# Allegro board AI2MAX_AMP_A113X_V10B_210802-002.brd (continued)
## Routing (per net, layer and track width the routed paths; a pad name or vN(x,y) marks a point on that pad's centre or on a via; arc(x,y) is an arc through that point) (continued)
VCC5V: length 175
  TOP w0.25: C10.2 R10.2 v2(22.85,10.2)
  TOP w0.3: v2(95.75,19.1) 95.75,19.25 95.35,19.65 94.25,19.65 93.45,18.85 88.6,18.85 88.35,19.1 88.1,19.1 87.5,19.7 85.1,19.7 v2(83.53,21.27) ; UNK5R5.1 79.35,41 80.1,40.25 80.1,38.4 v2(80.2,38.3)
  TOP w0.4: v2(52.05,9.95) v2(52.65,9.35) ; v2(62.15,9.95) v2(62.75,9.35)
  TOP w0.5: v2(52.65,9.95) 51.8,10.8 51.2,10.8 ; v2(52.65,9.95) v2(52.65,9.35) v2(52.05,9.35) ; v2(52.65,9.95) v2(52.05,9.95) ; 50.67,10.37 51.03,10.37 v2(51.45,9.95) ; 50.67,10.37 C57.1 ; 50.67,10.37 50.4,10.1 ; v2(51.45,9.35) v2(52.05,9.35) ; v2(51.45,9.35) 50.43,9.35 R52.2 ; v2(51.45,9.35) v2(51.45,9.95) ; v2(52.05,9.35) 52.05,9.65 ; 61.3,10.8 C68.1 ; 61.3,10.8 C69.2 U53.5 ; 61.3,10.8 v2(62.15,9.95) ; C68.1 62.15,10.45 v2(62.15,9.95) ; C68.1 61.9,10.8 v2(62.75,9.95) ; U52.5 C58.2 49.7,10.8 ; C57.1 50.35,10.8 ; C57.1 51.2,10.8 ; C57.1 51.45,10.45 v2(51.45,9.95) ; v2(51.45,9.95) 50.55,9.95 50.4,10.1 ; v2(51.45,9.95) v2(52.05,9.95) ; v2(62.15,9.95) v2(62.15,9.35) v2(62.75,9.35) v2(62.75,9.95) ; v2(62.15,9.95) v2(62.75,9.95) ; R52.2 50.4,10.1 ; R52.2 50.67,9.65 52.05,9.65 ; 50.4,10.1 49.7,10.8 ; 50.4,10.1 50.4,10.75 50.35,10.8 ; 49.7,10.8 50.35,10.8 ; 51.2,10.8 v2(52.05,9.95) ; v2(84.6,39.1) v2(84.6,32.3) v2(84.6,26.35) ; v2(52.05,9.95) 52.05,9.65
  MID2(L3) w0.3: v2(22.85,10.2) 22.85,13.95 24.05,15.15 35,15.15 v2(40.25,9.9)
  MID2(L3) w0.5: 63.35,9.95 v2(62.75,9.95) ; 63.35,9.95 v2(62.75,9.35) ; 63.35,9.95 63.7,9.95 ; v2(62.75,9.35) 63.1,9.35 63.7,9.95 ; v2(62.75,9.35) v2(62.15,9.35) ; v2(84.6,39.1) 81,39.1 v2(80.2,38.3) ; 64.05,9.95 62.85,8.75 ; 64.05,9.95 63.7,9.95 ; 64.05,9.95 68.75,9.95 79.33,20.52 82.78,20.52 v2(83.53,21.27) 83.95,21.7 83.95,23.6 84.6,24.25 v2(84.6,26.35)
  BOTTOM w0.1: v2(84.6,32.3) 84.4,32.1 R329.1 84.35,31.35 R330.1 ; 40.9,9.4 v2(40.9,9.9) 40.9,10 40.35,10 v2(40.25,9.9) v2(40.25,9.3) ; 40.9,9.4 v2(40.9,9.3) v2(40.9,8.7) v2(40.25,8.7) v2(40.25,9.3) ; 40.9,9.4 40.35,9.4 v2(40.25,9.3)
  BOTTOM w0.2: R337.2 v2(52.65,9.35) ; R6.2 41.85,7.55 R18.1
  BOTTOM w0.25: v2(40.25,9.9) 40.25,11 R17.1 ; C13.1 42.1,10.4 R6.2
  BOTTOM w0.4: v2(95.75,19.1) 95.75,11.95 97.6,10.1 100.2,10.1 102.75,7.55 UNK5C13.2 J814.1
  BOTTOM w0.5: U3.5 C14.2 ; U51.5 C52.2 C51.1 52.65,10.45 v2(52.65,9.95) ; v2(62.75,9.35) v2(62.15,9.35) v2(62.15,9.95) ; v2(62.75,9.35) v2(62.15,9.95) ; v2(62.75,9.35) v2(62.75,9.95) v2(62.15,9.95) ; v2(84.6,39.1) 85.6,38.1 R334.1
VCC_3.3V: length 71.6
  TOP w0.25: UNK4U5.24 56.14,29.71 UNK4C4.2 ; UNK4C5.1 44.64,29.31 UNK4U5.1 ; v2(50.08,52.33) 50.14,52.27 UNK4U5.37 ; UNK4U5.12 50.14,30.43 v2(50.05,30.34)
  TOP w0.254: v1(66.95,51.23) 66.89,51.17 U1.A5 ; v1(73.68,45.21) 73.39,44.92 U1.K15
  TOP w0.3: UNK4U9.T10 v2(51,40.6) 51.01,40.59 UNK4U9.U9 ; UNK4U9.N5 v2(49.5,42.1) 49.51,42.11 UNK4U9.M6 ; v2(56.15,28.8) UNK4C4.2
  TOP w0.406: v1(66.95,51.23) 66.95,52.78 66.14,53.6 v1(66.14,56.26)
  TOP w0.5: UNK4C4.2 57.35,29.7 57.65,30 v2(57.65,33) ; 44.65,29.05 v2(45.25,28.45) v2(44.65,28.45) 44.65,29.05 ; 44.65,29.05 UNK4C5.1 ; v2(85.2,51.7) v2(85.2,54.15) ; v2(45.5,62.35) v2(45.5,59.1)
  MID2(L3) w0.5: v2(85.2,51.7) 84.75,51.7 81.8,48.75 80.75,48.75 78.25,46.25 74.72,46.25 v1(73.68,45.21)
  BOTTOM w0.2: UNK2R18.1 v2(54.7,58.8) ; UNK2R19.1 v2(54.7,55.5)
  BOTTOM w0.3: UNK4C8.2 50.06,52.3 v2(50.08,52.33)
  BOTTOM w0.381: v1(73.68,45.21) 73.92,44.98 UNK5C10.2 ; UNK2C22.2 66.85,51.13 v1(66.95,51.23)
  BOTTOM w0.4: UNK4C17.2 v2(49.5,42.1) ; UNK4C18.2 51.25,40.35 v2(51,40.6)
  BOTTOM w0.5: UNK4R6.2 v2(54.25,36.05) 55.05,36.05 56.25,34.85 U55.1 C79.1 58,34.5 58,33.35 v2(57.65,33) 57.6,32.95 U55.3 ; 44.65,29.55 C22.1 Q1.3 ; 44.65,29.55 44.95,29.25 ; 44.65,29.55 v2(44.65,28.45) 44.95,28.45 ; v2(45.5,62.35) 44.5,63.35 UNK2T15.1 ; 44.95,29.25 45.25,28.95 v2(45.25,28.45) 44.95,28.45 ; 44.95,29.25 44.95,28.45 ; v2(56.15,28.8) 50.35,28.8 50.05,29.1 UNK4C49.2 v2(50.05,30.34)
VDD_EE: length 111.8
  TOP w0.2: R53.2 C64.2 UNK1R2.2 45.4,5.05 v2(45.2,5.05) ; v2(40,19.3) 40,22.45 v2(39.8,22.65)
  TOP w0.254: U1.J5 67.12,45.8 67.28,45.8 67.52,45.55 ; U1.J5 v1(66.56,45.86) U1.J4 v1(65.91,45.85) U1.J3 ; U1.J5 67.2,45.26 v1(67.22,45.29) 67.23,45.3 67.27,45.3 67.52,45.55 ; 67.52,45.55 U1.J6
  TOP w0.3: U1.K11 v1(70.47,45.24) ; U1.F12 v1(71.12,47.2)
  TOP w0.5: v2(57.65,45.75) v2(57.65,45.15)
  MID2(L3) w0.2: 51.65,15.5 51.35,15.2 ; 51.65,15.5 51.35,15.8 ; 51.65,15.5 51.65,15.2 ; 51.35,15.2 51.65,14.9 ; 51.35,15.2 v2(50.9,15.65) ; 51.35,15.2 51.65,15.2 ; 51.35,15.2 51.35,15.8 ; 51.65,14.9 51.65,15.2 ; 51.65,14.9 54.35,12.2 68.2,12.2 82.35,26.35 v2(83.1,26.35) ; v2(50.9,16.25) 51.35,15.8
  MID2(L3) w0.3: v1(70.47,45.24) 69.85,45.86 v1(66.56,45.86)
  BOTTOM w0.1: UNK2C13.1 61.58,45.51 61.44,45.65 ; 62.9,45.85 62.9,45.85 UNK2C11.2
  BOTTOM w0.2: 50.9,15.05 50.67,15.28 ; 50.9,15.05 50.9,15.5 ; 50.9,15.05 50.9,12.15 50.1,11.35 50.1,5.95 49.2,5.05 v2(45.2,5.05) ; 50.67,15.28 v2(50.3,15.65) ; 50.67,15.28 50.9,15.5 ; R15.2 38.8,18.1 v2(40,19.3) ; 50.9,15.5 v2(50.9,15.65) ; v2(83.1,26.35) 83.65,26.9 86.4,26.9 R333.2 ; v1(71.12,47.2) 71.35,46.96 UNK2R27.2 ; v2(39.8,22.65) v2(50.6,22.65)
  BOTTOM w0.3: UNK2C1.2 71.37,47.45 v1(71.12,47.2) 70.66,46.74 UNK2C16.2
  BOTTOM w0.381: UNK2C20.2 67.09,45.85 67.22,45.72 v1(67.22,45.29)
  BOTTOM w0.4: v1(70.47,45.24) 70.47,45.63 UNK2C16.2
  BOTTOM w0.5: v2(50.9,15.65) v2(50.3,15.65) v2(50.3,16.25) ; v2(50.9,15.65) v2(50.9,16.25) v2(50.3,16.25) ; v2(50.9,15.65) v2(50.3,16.25) ; 58.15,45.65 v2(57.65,45.15) v2(57.65,45.75) 57.8,45.9 59.15,45.9 59.15,45.65
  BOTTOM w0.508: 61.58,45.52 61.58,45.85 v1(65.91,45.85) UNK2C20.2
  BOTTOM w1.016: 58.15,45.65 61.44,45.65
VDDAO_3.3V: length 209
  TOP w0.1: v2(38.5,22.95) 38.5,23.65 38.9,24.05 R350.1 R351.1 ; UNK2R28.1 UNK2R24.1 v2(79.95,59.8)
  TOP w0.2: 43.33,15.28 v2(42.95,15.65) ; 43.33,15.28 43.55,15.05 ; 43.33,15.28 43.55,15.5 ; v2(45.2,5.92) 44.42,5.92 44,6.35 44,13.3 43.55,13.75 43.55,15.05 ; 43.55,15.5 v2(43.55,15.65) ; 43.55,15.5 43.55,15.05 ; R62.1 63.3,8.4 63.75,8.85 v2(63.75,11.2)
  TOP w0.25: R348.1 R349.1 93.55,59.1 v2(92.7,58.25)
  TOP w0.254: v1(73.07,44.59) U1.K14 ; U1.D13 72.09,48.82 v1(71.77,49.15)
  TOP w0.3: v2(61.6,61.45) UNK2D7.1 ; v2(92.7,58.25) 92.85,58.1 92.85,49.8 v2(92.95,49.7)
  TOP w0.4: v2(60.15,58) 60.15,57.2 60.55,56.8 60.55,52.95 v2(61.25,52.25)
  TOP w0.5: v3(74.05,56.05) 74.05,57.2 UNK2U2.3 74.73,59.37 v2(74.55,59.55) UNK2C15.2 ; v2(83.95,37.9) v2(83.95,32.3) v2(83.95,27.35) ; v2(43.55,16.25) v2(42.95,16.25) v2(42.95,15.65) ; v2(43.55,16.25) v2(42.95,15.65) ; v2(43.55,16.25) v2(43.55,15.65) v2(42.95,15.65) ; v2(51.2,71.4) v2(50.6,71.4) ; v2(43.35,34.55) v2(43.35,35.15)
  MID2(L3) w0.2: v2(92.95,49.7) 92.55,49.3 92.55,42.8 87.65,37.9 v2(83.95,37.9) ; 43.7,14.9 43.4,15.2 ; 43.7,14.9 43.7,12.55 45.05,11.2 v2(63.75,11.2) ; 43.7,14.9 43.7,15.2 ; 43.4,15.2 43.7,15.2 ; 43.4,15.2 v2(42.95,15.65) ; 43.4,15.2 43.7,15.5 ; 43.4,15.2 43.4,15.5 v2(43.55,15.65) 43.7,15.5 ; 43.7,15.2 43.7,15.5
  MID2(L3) w0.5: 51.2,70.8 v2(51.2,71.4) v2(50.6,71.4) 51.2,70.8 ; 51.2,70.8 52.2,69.8 52.2,61 ; UNK2CON1.3 66.35,71.42 66.35,61.7 ; v2(83.95,27.35) 84.3,27.7 v2(93.35,27.7) 94.52,27.7 v2(96.1,26.12)
  BOTTOM w0.1: R336.1 81.5,32.3 v2(83.95,32.3)
  BOTTOM w0.2: v2(96.1,26.12) 96.12,26.14 R214.2 ; C19.2 R8.2 47.5,6.8 46.63,5.92 v2(45.2,5.92) ; R314.2 33.93,59.01 v2(33.95,59.03) ; R323.1 33.93,47.07 v2(33.95,47.05) ; v2(33.95,25.1) 33.93,25.12 R307.1
  BOTTOM w0.254: v1(71.77,49.15) 71.86,49.18 72.51,49.84 UNK2C5.2
  BOTTOM w0.3: U201.40 94.68,50.08 C201.1 92.96,49.69 v2(92.95,49.7) ; UNK2C5.2 73.48,51.28 73.48,51.28 ; v2(36.8,57.4) C330.1 35.37,57.01 U302.40 ; U301.40 35.37,35.06 C301.1 v2(36.55,35.45) ; U202.40 94.68,28.13 C230.1 93.39,27.74 v2(93.35,27.7)
  BOTTOM w0.305: C101.2 75.59,44.45 73.21,44.45 v1(73.07,44.59)
  BOTTOM w0.4: v2(78.55,61) 77.66,61 T129.1 T319.1 ; v2(61.25,52.25) 63.11,50.39 UNK2R2.1
  BOTTOM w0.5: 42.7,34.5 42.05,33.85 41.8,33.85 ; 42.7,34.5 41.8,34.5 ; 42.7,34.5 43.1,34.9 ; 43.1,34.9 R12.2 41.8,34.5 ; 43.1,34.9 v2(43.35,35.15) v2(43.35,34.55) 42.65,33.85 C21.1 ; 41.8,33.85 C23.2 C21.1 ; 41.8,33.85 41.8,34.5 ; v2(50.6,71.4) v2(51.2,71.4) C249.1 51.85,71.35 C250.2 51.85,67.9 T316.1 ; 41.8,34.5 C21.1 ; C21.1 42.65,32.3 Q1.2 ; v2(83.95,37.9) 83.95,37.3 R335.1 83.65,37.15 82.7,36.2 79.8,36.2 79.3,36.7 79.3,39.4 77.27,41.43 77.27,42.77 C101.2 ; R105.1 62.7,56.86 v2(62.7,57.85)
  BOTTOM w0.508: v3(74.05,56.05) 74.32,55.78 74.32,52.12 73.48,51.28
VDDCPU: length 53.9
  TOP w0.2: v1(67.18,47.2) 67.21,47.2 ; 67.21,47.2 U1.F6 67.54,47.52 67.86,47.2 67.86,47.19 U1.G6 ; 67.21,47.2 U1.G5 ; 67.21,47.2 U1.F5 66.56,47.2 ; 67.21,47.2 U1.G6 ; v2(53.8,15.05) 53.8,14.55 54.4,13.95 54.4,6.65 54.75,6.3 v2(58.95,6.3) ; v1(67.83,46.59) 67.87,46.55 67.86,46.55 U1.G6 ; 66.56,46.55 U1.G5 ; 66.56,46.55 U1.H4 v1(65.92,46.6) ; 66.56,46.55 U1.H5 U1.G6 ; 66.56,46.55 66.4,46.71 ; 66.56,46.55 v1(66.58,46.59) ; U1.G5 67.21,46.59 v1(67.19,46.59) ; U1.G5 66.56,47.2 ; v1(65.92,46.6) U1.G4 ; v1(65.92,46.6) U1.H3 ; v1(65.92,46.6) U1.G3 65.59,46.87 v1(65.91,47.2) U1.G4 ; U1.G4 66.4,46.71 ; U1.G4 66.4,46.71 ; U1.G4 66.56,47.2
  TOP w0.5: v2(53.2,16.25) v2(53.2,15.65) ; v2(53.2,16.25) v2(53.8,15.65) ; v2(53.2,16.25) v2(53.8,16.25) v2(53.8,15.65) ; v2(53.2,15.65) v2(53.8,15.05) ; v2(53.2,15.65) v2(53.2,15.05) v2(53.8,15.05) ; v2(53.2,15.65) v2(53.8,15.65) ; v2(57.45,50.7) v2(58.05,50.1) ; v2(57.45,50.7) v2(57.45,50.1) v2(58.05,50.1) ; v2(57.45,50.7) v2(58.05,50.7) ; v2(58.05,50.1) v2(58.65,50.1) ; v2(58.05,50.1) v2(58.05,50.7) ; v2(58.05,50.7) v2(58.65,50.7) v2(58.65,50.1) ; v2(58.05,50.7) v2(58.65,50.1) ; v2(53.8,15.05) v2(53.8,15.65)
  BOTTOM w0.1: v1(65.92,46.6) 65.91,46.61 v1(65.91,47.2) ; v1(67.18,47.2) UNK2C19.2 ; 66.7,46.54 66.65,46.59 v1(66.58,46.59) ; UNK2C6.1 UNK2C4.1 ; 63.2,46.89 63.22,46.91 UNK2C7.2 ; 65.4,46.89 65.38,46.91 UNK2C14.2 ; UNK2C8.2 64.31,46.9 64.3,46.89
  BOTTOM w0.102: 67.84,46.56 67.82,46.55 ; 67.84,46.56 67.83,46.57 ; 67.84,46.56 67.85,46.55 67.84,46.56 ; 67.84,46.56 v1(67.83,46.59) ; 67.84,46.56 67.84,46.56 ; 67.82,46.55 67.79,46.51 ; 67.82,46.55 v1(67.83,46.59) ; 67.84,46.56 v1(67.83,46.59) ; 67.84,46.56 67.94,46.66 v1(67.83,46.59) ; 67.51,46.89 67.83,46.57 ; v1(67.83,46.59) 67.83,46.57
  BOTTOM w0.2: v1(67.83,46.59) 67.71,46.7 UNK2C19.2 ; UNK2C2.2 66.57,47.01 66.7,46.89 ; v2(58.95,6.3) 58.05,6.3 UNK1R1.2 R51.2 C63.2
  BOTTOM w0.254: 65.93,46.54 65.93,46.65 v1(65.92,46.6) 65.93,46.54 ; 65.93,46.54 66.34,46.54 66.7,46.89
  BOTTOM w0.406: 67.86,46.61 67.86,46.59 v1(67.83,46.59) 67.84,46.57
  BOTTOM w0.508: v1(67.19,46.59) v1(67.83,46.59) ; v1(67.83,46.59) 67.82,46.58 ; v1(67.83,46.59) 67.79,46.51 67.76,46.54 66.34,46.54
  BOTTOM w1.27: UNK2C4.1 62.13,46.89 67.51,46.89
VDDCPU_EN: length 97.4
  TOP w0.1: v2(60.25,51.85) 60.05,52.05 57.75,52.05 56.85,52.95 56.85,55.65 56.15,56.35 56.15,57.5 55.3,58.35 54.2,58.35 v2(53.55,59) ; v2(52,7.45) 53.05,7.45 53.6,8 53.6,13.2 52.3,14.5 52.3,16.8 53.95,18.45 v2(53.95,23.9) ; v2(41.5,56.25) 42.15,55.6 42.15,27.25 43,26.4 v2(43,23.7)
  TOP w0.102: U1.C4 v1(65.91,49.8)
  BOTTOM w0.1: v1(65.91,49.8) 65.31,50.4 64.26,50.4 UNK2R2.2 63.76,49.89 62.94,49.89 60.97,51.85 v2(60.25,51.85) ; v2(43,23.7) 43.3,23.4 48.5,23.4 49,23.9 v2(53.95,23.9) ; v2(41.5,56.25) 41.5,56.75 42,57.25 52.8,57.25 53.55,58 v2(53.55,59)
  BOTTOM w0.2: R54.1 v2(52,7.45)
VDDCPU_PWM: length 94.4
  TOP w0.1: v2(43.2,4.6) 42.95,4.85 42.95,12.6 41.65,13.9 41.65,22.95 40.95,23.65 40.95,53.75 v2(40.75,53.95)
  TOP w0.102: v1(65.26,49.15) U1.D3
  BOTTOM w0.1: v2(40.75,53.95) 42.35,53.95 43.85,55.45 52.8,55.45 54.05,54.2 56.25,54.2 60.3,50.15 62.02,50.15 62.85,49.32 65.09,49.32 v1(65.26,49.15)
  BOTTOM w0.2: UNK1R1.1 R56.2 56.9,4.85 56.25,4.2 43.6,4.2 v2(43.2,4.6)
VDDEE_PWM: length 84
  TOP w0.1: v2(40.75,54.95) 40.95,54.95 41.55,54.35 41.55,24.25 42.15,23.65 42.15,14.2 43.45,12.9 43.45,5.7 44.6,4.55 45.55,4.55 46.05,5.05 UNK1R2.1 R58.2
  TOP w0.102: v1(65.91,49.15) U1.D4
  BOTTOM w0.1: v2(40.75,54.95) 42.55,54.95 43.55,55.95 53.01,55.95 54.26,54.7 56.45,54.7 60.25,50.9 61.61,50.9 62.95,49.56 65.5,49.56 v1(65.91,49.15)
VDDIO_AO18: length 88.9
  TOP w0.254: v1(71.77,45.9) U1.H13 72.33,45.97 v1(72.33,45.9) 72.33,45.81 U1.J13 71.96,45.7 v1(71.77,45.9) ; v1(71.77,45.9) U1.J12 ; v1(71.77,45.9) U1.H12
  TOP w0.5: v2(85.95,54.1) v2(85.95,51.7) 85.95,47.3 84.55,45.9 84.55,40.85 v2(83.95,40.25)
  MID2(L3) w0.5: v2(61.57,57.85) 62.32,57.1 69,57.1 69.8,57.9 74.58,57.9 v3(75.28,57.2) 76.43,56.05 84.3,56.05 85.95,54.4 v2(85.95,54.1)
  BOTTOM w0.1: v1(71.77,45.9) 71.77,45.9 v1(72.33,45.9) ; 74.6,46.26 UNK3C1.2 ; UNK2C17.1 77.04,46.27 77.05,46.28
  BOTTOM w0.254: UNK5C9.2 72.09,45.7 72.68,45.7 72.87,45.9
  BOTTOM w0.3: UNK2R29.2 79.45,49.05 81.55,51.15 85.4,51.15 v2(85.95,51.7)
  BOTTOM w0.4: UNK5C9.2 71.77,45.5 v1(71.77,45.9) 72.87,45.9 72.88,45.9
  BOTTOM w0.406: 72.88,45.9 UNK2C10.2
  BOTTOM w0.5: U54.5 C76.1 UNK5R20.1 ; v2(61.57,57.85) R106.1 ; v2(83.95,40.25) UNK5R20.1 ; UNK5R20.1 82.25,41.26 79.6,43.91 79.6,44.91
  BOTTOM w0.508: 75.34,46.26 UNK2C12.2 ; 75.34,46.26 74.6,46.26 74.32,45.98 ; 75.34,46.26 75.24,46.16 ; 75.34,46.26 76.68,46.26 76.78,46.16 ; UNK2C10.2 72.95,45.98 74.32,45.98 ; 74.32,45.98 75.05,45.98 75.24,46.16 ; v3(75.28,57.2) 75.61,56.87 75.61,53.93 UNK2R3.2 ; 76.78,46.16 UNK2C17.1 ; 76.78,46.16 75.24,46.16
  BOTTOM w0.61: 78.33,46.18 77.72,46.18 77.61,46.28 ; 78.33,46.18 79.6,44.91 79.6,45.42 78.45,46.56 UNK2C12.2 ; 78.33,46.18 78.23,46.28 77.61,46.28 ; 77.61,46.28 77.05,46.28
VDDIO_BOOT: length 92.4
  TOP w0.2: UNK4U9.Y4 UNK4U9.AA5 v2(49.01,36.95) ; UNK4U9.Y4 UNK4U9.W4 ; UNK4U9.Y4 UNK4U9.AA3 v2(48.01,36.95) ; UNK4R3.1 UNK4R8.1 51.49,54.48 v2(51.61,54.36)
  TOP w0.25: v2(54.8,53.46) UNK4C11.2 54.64,52.59 UNK4U5.28 ; v2(45.65,52.45) 46.14,51.96 UNK4U5.45
  TOP w0.254: UNK4U5.34 51.64,53.57 UNK4C10.2 51.61,53.64 v2(51.61,54.36)
  TOP w0.3: v2(49.7,43.1) 49.51,43.29 UNK4U9.K6 ; v1(65.32,44.53) 65.58,44.27 U1.L3
  TOP w0.5: v2(58.75,41.65) 58.25,41.15 v2(58.25,37.45) ; v2(43.95,38.95) v2(43.95,44.25) v2(43.95,51.3)
  MID2(L3) w0.5: 48.2,36.95 v2(49.01,36.95) 50.15,36.95 50.95,36.15 v2(50.95,35.2) ; 48.2,36.95 v2(48.01,36.95) 46.2,38.76 ; 48.2,36.95 v2(46.2,38.95) ; 46.01,38.95 v2(46.2,38.95) ; 46.01,38.95 46.2,38.76 ; 46.01,38.95 v2(43.95,38.95) ; v2(46.2,38.95) 46.2,38.76 ; v2(49.7,43.1) 49.7,43.9 49.35,44.25 43.95,44.25 v2(43.95,44.25)
  BOTTOM w0.1: v2(50.95,35.2) 50.95,31.9 UNK4R4.1 ; UNK4R12.2 v2(46.2,38.95) ; UNK4C34.2 50.25,43.6 UNK4R16.1
  BOTTOM w0.2: v2(48.01,36.95) 47.55,36.49 UNK4R14.1 UNK4R1.2 48.65,36.95
  BOTTOM w0.4: v2(58.75,41.65) 60.35,41.65 60.9,42.2 61.72,42.2 63.03,43.51 63.47,43.51 UNK4C2.2 64.49,44.19 64.83,44.53 v1(65.32,44.53) ; UNK4C34.2 49.8,43.2 v2(49.7,43.1)
  BOTTOM w0.5: v2(43.95,51.3) 44.45,51.8 UNK4C48.2 v2(45.65,52.45) 45.65,52.75 46.48,53.58 49.37,53.58 50.15,54.36 v2(51.61,54.36) 52.14,54.36 53.04,53.46 v2(54.8,53.46) ; v2(58.25,37.45) 57.75,36.95 UNK4R6.1 UNK4R5.1 UNK4C47.1 UNK4C35.2 v2(49.01,36.95) v2(48.01,36.95)
VDDIO_X: length 12.4
  TOP w0.254: U1.C8 68.84,49.47 v1(69.16,49.8)
  BOTTOM w0.4: v1(69.16,49.8) 69.16,50.14 68.6,50.7 C102.2 68.6,53.5 68.1,54 66.75,54 65.2,55.55 63.4,55.55 63.01,55.94 R105.2 R106.2
VDDQ1.35V: length 76.3
  TOP w0.2: 70.18,32.73 v1(70.56,32.35) 70.15,31.94 UNK3U1.E9 v1(69.77,32.31) 70.15,32.69 UNK3U1.D9 70.18,32.73 ; 70.18,32.73 70.2,32.73 v1(70.62,33.15) 70.53,33.15 UNK3U1.C9 ; v1(70.62,29.59) 70.21,29.59 70.15,29.54 UNK3U1.H9 ; UNK3U1.F1 63.54,31.13 63.28,31.4 63.27,31.4 v1(63.23,31.43) ; U1.M11 v1(70.47,43.94) U1.M10 ; UNK3U1.R9 70.16,23.94 70.68,23.94 v1(70.68,23.94) ; U1.M6 v1(67.86,43.29) U1.M7 68.19,43.62 v1(68.51,43.29) U1.M8 ; v1(70.67,25.53) 70.67,25.53 UNK3U1.N9 ; UNK3U1.C1 63.15,33.53 v1(63.15,33.53) ; UNK3U1.H2 v1(64.19,29.17) ; v1(68.91,35.54) 68.94,35.54 UNK3U1.A8 ; v1(63.19,23.83) 63.29,23.93 UNK3U1.R1 ; UNK3U1.A1 63.76,35.13 v1(64.15,34.74) 64.55,34.34 UNK3U1.B2 v1(64.92,34.7) ; v1(68.12,30.71) 68.17,30.71 UNK3U1.G7 68.27,30.05 v1(68.09,30.05) ; UNK3U1.K2 64.55,27.94 v1(64.92,28.31) ; C74.2 R61.2 59.45,7.35 60,6.8 v2(60,6.3) ; v1(68.94,27.52) UNK3U1.K8 ; 66.89,42.97 U1.N5 v1(66.56,42.64) 66.24,42.97 U1.N4 v1(66.56,43.29) 66.89,42.97
  TOP w0.3: v1(63.18,25.52) 63.74,25.52 UNK3U1.N1 ; UNK3U1.D2 64.94,32.34 v1(64.96,32.34)
  BOTTOM w0.2: 61,13.15 61,7.3 v2(60,6.3) ; 61,13.15 61.23,13.38 ; 61,13.15 61,13.6 ; 61.23,13.38 61,13.6 ; 61.23,13.38 v2(61.6,13.75) ; 61,13.6 v2(61,13.75)
  BOTTOM w0.3: 70.86,33.39 UNK3C58.2 70.73,33.96 70.6,33.96 ; 70.86,33.39 v1(70.62,33.15) 70.32,32.85 UNK3C38.2 ; 70.86,33.39 70.86,32.65 70.6,32.39 ; 70.1,32.35 70.3,32.55 70.3,33.96 ; 70.1,32.35 69.81,32.35 ; 70.1,32.35 v1(70.56,32.35) 70.6,32.39 ; UNK3C38.2 69.8,33.95 UNK3C42.2 70.1,33.96 ; UNK3C38.2 69.77,32.82 v1(69.77,32.31) 69.81,32.35 ; 70.6,32.39 70.6,33.96 ; 70.1,33.96 70.3,33.96 ; 70.1,33.96 70.1,32.64 69.81,32.35 ; v1(63.15,33.53) 63.5,33.18 UNK3C21.2 ; v1(70.47,43.94) 71.04,43.37 UNK3C4.2 ; 70.6,33.96 70.3,33.96
  BOTTOM w0.381: v1(63.23,31.43) 62.92,31.74 UNK3C2.2
  BOTTOM w0.4: UNK3C9.2 64.15,35.12 v1(64.15,34.74) ; UNK3C30.2 71.12,25.53 v1(70.67,25.53) ; UNK3C19.2 63.88,29.49 v1(64.19,29.17) ; UNK3C12.2 70.42,24.21 v1(70.68,23.94) ; 66.56,42.71 66.56,43.16 ; 66.56,42.71 67.03,43.18 UNK3C39.2 ; 66.56,42.71 v1(66.56,42.64) 65.66,42.64 UNK3C62.2 ; 66.56,43.16 v1(66.56,43.29) 66.63,43.36 UNK3C39.2 ; 66.56,43.16 66.05,42.65 ; UNK3C39.2 66.32,42.65 66.05,42.65 ; UNK3C18.2 63.16,25.5 v1(63.18,25.52) 63.3,25.52 UNK3C6.1 ; UNK3C28.1 63.15,40.28 UNK3C31.2 64.85,41.85 UNK3C62.2 ; UNK3C62.2 66.05,42.65 ; v1(70.62,29.59) 70.12,29.59 UNK3C45.2 ; v1(68.12,30.71) 67.66,30.71 UNK3C8.1 67.56,30.05 v1(68.09,30.05) ; v1(64.92,34.7) 64.92,35.18 UNK3C10.2 ; v1(61.44,26.9) 61.44,27.49 UNK3R19.2 61.37,27.56 v1(60.84,27.56) ; v1(64.96,32.34) 65.01,32.28 UNK3C11.2 ; v1(64.92,28.31) 64.92,28.7 UNK3C26.1
  BOTTOM w0.406: v1(68.51,43.29) 67.87,43.29 v1(67.86,43.29)
  BOTTOM w0.5: v1(68.91,35.54) 69.01,35.64 UNK3C20.2 ; 63.19,23.42 63.67,23.42 UNK3R8.2 ; 63.19,23.42 UNK3C35.2 ; 63.19,23.42 v1(63.19,23.83) ; UNK3R8.2 63.65,23.37 v1(63.19,23.83) ; UNK3R8.2 63.72,24.24 ; v2(61.6,13.75) v2(61,13.75) v2(61,14.35) ; v2(61.6,13.75) v2(61,14.35) ; v2(61.6,13.75) v2(61.6,14.35) v2(61,14.35) ; v1(68.51,43.29) 68.48,43.33 UNK3C5.2 ; UNK3C26.1 65.2,29.2 64.7,29.7 UNK3C19.2 ; v1(63.19,23.83) 63.31,23.83 63.72,24.24 ; 63.72,24.24 UNK3C6.1
  vias: v4(60.83,38.06) v4(60.85,39.07)
ACTIVE_STBY: length 123.9
  TOP w0.1: v2(59.5,24.2) 59.8,24.2 60.35,23.65 60.35,23.25 66,17.6 66,17.15 66.25,16.9 66.8,16.9 v2(67.2,16.5) ; v2(44.8,25.4) 44.3,25.9 43.8,25.9 42.35,27.35 42.35,56.05 v2(42.15,56.25) ; U1.B11 71.12,50.45 71.12,50.93 70.68,51.36 70.68,54.98 71.45,55.75 71.45,58.85 v2(71.25,59.05) ; v2(78.14,15.5) 78.3,15.5 79.1,16.3 85.95,16.3 87.5,14.75 R219.1
  BOTTOM w0.1: v2(71.25,59.05) 57.25,59.05 56.95,59.35 54.6,59.35 54.3,59.05 54.3,58.15 53,56.85 42.75,56.85 v2(42.15,56.25) ; v2(67.2,16.5) 67.4,16.3 76.64,16.3 77.04,15.9 77.74,15.9 v2(78.14,15.5) ; R320.1 44.25,25.95 v2(44.8,25.4) 44.8,24.8 45.3,24.3 47.2,24.3 48.5,25.6 57.5,25.6 58.5,24.6 59.1,24.6 v2(59.5,24.2)
AMP_RESET: length 105.2
  TOP w0.1: v2(67.2,17.3) 66.8,17.7 66.47,17.7 60.75,23.42 60.75,23.85 59.6,25 v2(59.5,25) ; v2(42.35,60.2) 42.2,60.05 42.2,57.45 42.75,56.9 42.75,27.55 43.95,26.35 46.8,26.35 v2(47.15,26) ; R215.1 v2(88.5,13.4) 88.5,14.35 86.15,16.7 78.8,16.7 78.4,16.3 v2(78.14,16.3)
  BOTTOM w0.1: v2(67.2,17.3) 67.25,17.3 67.85,16.7 77.74,16.7 v2(78.14,16.3) ; v2(42.35,60.2) 42.1,59.95 40.35,59.95 40.05,60.25 40.05,63.9 42.8,66.65 48.1,66.65 48.58,67.12 ; R315.1 v2(47.15,26) 58.5,26 v2(59.5,25) ; UNK5R74.2 v2(88.5,13.4)
  BOTTOM w0.3: T317.1 48.58,67.12
AMP_SCL: length 67.5
  TOP w0.1: UNK2R24.2 v2(81.5,59.05) ; v2(87.25,59) 87.25,57.8 87.8,57.25 87.8,54.25 88.35,53.7 88.35,48.25 88.6,48 88.6,33.55 89.4,32.75 89.4,20.1 v2(89.6,19.9)
  TOP w0.102: U1.A16 74.04,51.69 75.8,53.46 75.8,54.57 78.36,57.14 81.24,57.14 81.9,57.8 81.9,58.65 v2(81.5,59.05)
  BOTTOM w0.1: UNK5R66.2 87.4,15.6 86.7,16.3 86.7,18.25 88.15,19.7 89.4,19.7 v2(89.6,19.9) ; v2(87.25,59) 86.25,59 85.65,59.6 82.85,59.6 R209.1 v2(81.5,59.05)
AMP_SCL_DEV: length 66.1
  TOP w0.1: v2(43.3,60.9) 43.05,60.65 43.05,59.45 v2(42.65,59.05) ; v2(52.3,58.45) 52.3,58.25 52.85,57.7 R309.1 ; v2(83.8,61.3) 83.95,61.15 83.95,59.25 v2(83.75,59.05)
  BOTTOM w0.1: v2(43.3,60.9) 43.7,61.3 43.7,63.85 44.1,64.25 52.6,64.25 53.15,64.8 68.15,64.8 69.15,65.8 69.7,65.8 70.6,66.7 74.55,66.7 75.7,67.85 76.1,67.85 ; v2(83.8,61.3) 83.6,61.5 81.7,61.5 79.1,64.1 79.1,66.8 78.05,67.85 77.7,67.85 ; R238.1 v2(83.75,59.05) R209.2 ; v2(42.65,59.05) 43.05,58.65 43.5,58.65 43.65,58.5 44.2,58.5 44.65,58.05 51.9,58.05 v2(52.3,58.45)
  BOTTOM w0.3: 76.1,67.85 T306.1 77.7,67.85
AMP_SDA: length 69.5
  TOP w0.1: v2(90.25,19.9) 89.6,20.55 89.6,32.87 88.8,33.67 88.8,48.15 88.55,48.4 88.55,53.8 88.01,54.34 88.01,57.74 v2(87.75,58) ; 78.27,57.35 80.25,57.35 UNK2R28.2 v2(81.5,57.95)
  TOP w0.102: U1.B15 73.39,50.27 73.71,50.59 73.71,51.67 75.59,53.55 75.59,54.66 78.27,57.35
  BOTTOM w0.1: v2(87.75,58) 87.55,58.2 86.5,58.2 85.7,57.4 82.85,57.4 R210.1 v2(81.5,57.95) ; UNK5R65.2 87.4,13.3 87.95,13.85 87.95,15.35 86.9,16.4 86.9,18.15 88.25,19.5 89.85,19.5 v2(90.25,19.9)
AMP_SDA_DEV: length 69.4
  TOP w0.1: R310.1 52.5,57.1 52.5,57.45 51.7,58.25 v2(51.7,58.45) ; v2(84.45,61.3) 84.15,61 84.15,58.35 v2(83.75,57.95) ; v2(43.3,61.5) 43.7,61.1 43.7,60.7 43.25,60.25 v2(43.25,59.05)
  BOTTOM w0.1: R210.2 v2(83.75,57.95) R239.1 ; v2(84.45,61.3) 84.05,61.7 81.8,61.7 79.3,64.2 79.3,67.2 ; 78.72,68.42 78.5,68.65 76.2,68.65 74.45,66.9 70.5,66.9 69.6,66 69.05,66 68.05,65 53.05,65 52.5,64.45 43.95,64.45 43.5,64 43.5,61.7 v2(43.3,61.5) ; v2(43.25,59.05) 43.4,59.05 43.75,58.7 44.35,58.7 44.8,58.25 51.5,58.25 v2(51.7,58.45)
  BOTTOM w0.3: 78.72,68.42 T305.1 79.3,67.2
BCLK: length 5.7
  BOTTOM w0.102: UNK5R68.1 85,10.75 86.15,9.6 87.8,9.6 88.68,8.72 J813.11
CPU_RESET: length 126.6
  TOP w0.1: U1.A12 71.44,50.94 71.13,51.25 71.13,51.56 71.39,51.83 71.39,54.63 72.23,55.47 UNK2R14.1 72.24,56.64 UNK2U2.2 71.85,57.61 71.85,59.15 72.05,59.35 v2(72.05,59.65) ; v2(78.15,17.1) 86.35,17.1 88.2,15.25 90.4,15.25 R240.1 ; v2(59.5,25.7) 60.95,24.25 60.95,23.52 66.57,17.9 67.4,17.9 v2(68,17.3) ; v2(44.05,58.05) 44.05,57.65 43.35,56.95 43.35,36.8 43.8,36.35 43.8,34.35 43.15,33.7 43.15,27.6 44.1,26.65 46.75,26.65 v2(47.15,27.05)
  BOTTOM w0.1: v2(68,17.3) 68.4,16.9 77.95,16.9 v2(78.15,17.1) ; R338.1 47.1,27.1 v2(47.15,27.05) 48,26.2 59,26.2 v2(59.5,25.7) ; v2(44.05,58.05) 44.25,57.85 52.45,57.85 52.75,58.15 52.75,59.4 53.2,59.85 53.85,59.85 54.15,60.15 57.4,60.15 57.7,59.85 65.4,59.85 65.8,60.25 66.95,60.25 67.55,59.65 70.1,59.65 70.5,60.05 71.65,60.05 v2(72.05,59.65)
CTRL_A113X: length 2.8
  BOTTOM w0.1: UNK5R75.2 UNK5R77.1 UNK5R76.1
DATA: length 8.3
  BOTTOM w0.102: J813.12 88.18,8.72 87.6,9.3 85.85,9.3 84.5,10.65 84.5,13.7 UNK5R69.1
DDR3_A0: length 28.5
  TOP w0.102: v1(71.12,41.34) U1.R12 ; UNK3U1.N3 65.78,25.53 66.58,24.73 v1(67.05,24.73)
  BOTTOM w0.102: v1(71.12,41.34) 71.12,41.21 70.76,40.86 70.76,40.62 71.04,40.34 71.29,40.34 72.41,39.22 73.17,39.22 75.04,37.35 75.04,26.89 73.05,24.89 72.26,24.89 72.03,25.12 70.35,25.12 70.23,25 67.32,25 v1(67.05,24.73)
DDR3_A1: length 24.7
  TOP w0.1: v1(68.94,24.35) 68.56,24.73 UNK3U1.P7
  TOP w0.102: U1.U15 73.45,40.31 73.45,39.68 75.62,37.51 75.62,26.66 72.6,23.64 v1(72.4,23.64)
  BOTTOM w0.102: v1(72.4,23.64) 72.4,23.43 71.7,22.74 69.85,22.74 69.31,23.27 69.31,23.98 v1(68.94,24.35)
DDR3_A2: length 34.8
  TOP w0.102: v1(74.37,41.99) U1.P16 ; UNK3U1.P3 65.72,24.73 66.15,24.3 v1(66.15,23.76)
  BOTTOM w0.102: v1(74.37,41.99) 74.77,41.59 74.77,41.3 75.26,40.82 75.81,40.82 77.8,38.84 77.8,25.76 72.92,20.88 69.59,20.88 66.71,23.76 v1(66.15,23.76)
DDR3_A3: length 35.7
  TOP w0.102: U1.U17 76.93,38.13 76.93,26.11 71.98,21.16 65.91,21.16 64.86,22.21 64.1,22.21 62.84,23.47 62.84,24.98 63,25.15 63.89,25.15 64.27,25.53 UNK3U1.N2
DDR3_A4: length 24.6
  TOP w0.102: UNK3U1.P8 69.74,25.12 71.45,25.12 v1(71.85,25.53) ; v1(71.04,41.94) 70.79,41.69 U1.R11
  BOTTOM w0.102: v1(71.04,41.94) 70.76,41.66 70.76,41.23 70.47,40.93 70.47,40.55 70.9,40.12 71.15,40.12 72.29,38.98 73.05,38.98 74.75,37.29 74.75,27 72.92,25.17 72.4,25.17 72.04,25.53 v1(71.85,25.53)
DDR3_A5: length 30.3
  TOP w0.102: U1.T14 72.67,40.94 72.67,40.77 72.44,40.54 72.44,40.23 72.61,40.06 72.79,40.06 72.94,39.91 72.94,39.45 75.04,37.35 75.04,26.89 72.77,24.61 72.36,24.61 71.65,23.9 71.65,23.12 71.27,22.74 66.59,22.74 66.37,22.96 66.37,23.4 66.53,23.56 66.53,24.35 65.74,25.14 65.12,25.14 64.72,24.73 UNK3U1.P2
DDR3_A6: length 24.4
  TOP w0.102: v1(71.89,24.68) 71.55,24.34 69.76,24.34 UNK3U1.R8 ; v1(71.77,41.99) U1.P12
  BOTTOM w0.102: v1(71.77,41.99) 71.77,40.98 75.33,37.42 75.33,26.77 73.17,24.61 71.95,24.61 v1(71.89,24.68)
DDR3_A7: length 29.3
  TOP w0.102: UNK3U1.R2 64.94,24.32 65.58,24.32 65.74,24.16 65.74,23.21 66.49,22.46 71.42,22.46 71.95,22.99 71.95,23.8 72.49,24.34 72.89,24.34 75.33,26.77 75.33,37.42 73.2,39.55 73.2,40.06 72.9,40.35 72.74,40.35 U1.U14
DDR3_A8: length 25.1
  TOP w0.102: v1(71.27,23.93) 70.89,23.55 69.77,23.55 UNK3U1.T8 ; U1.P13 72.35,42.06 v1(72.35,42.04)
  BOTTOM w0.102: v1(72.35,42.04) 72.06,41.74 72.06,41.07 75.62,37.51 75.62,26.66 73.27,24.31 71.9,24.31 71.52,23.93 v1(71.27,23.93)
DDR3_A9: length 31.6
  TOP w0.102: UNK3U1.R3 64.97,23.55 64.97,22.91 65.12,22.76 65.12,22.35 66.04,21.44 71.88,21.44 76.63,26.19 76.63,38.03 74.65,40.01 74.57,40.01 74.37,40.21 74.37,40.69 U1.T16
DDR3_A10: length 22.8
  TOP w0.102: v1(70.4,41.42) 70.39,41.42 70.14,41.67 U1.R10 ; UNK3U1.L7 68.93,26.75 73.22,26.75 v1(73.5,27.03)
  BOTTOM w0.102: v1(70.4,41.42) 70.16,41.18 70.16,40.49 70.8,39.85 71.06,39.85 72.2,38.72 72.91,38.72 74.44,37.19 74.44,27.97 v1(73.5,27.03)
DDR3_A11: length 35.3
  TOP w0.102: UNK3U1.R7 68.55,23.67 67.92,23.04 66.85,23.04 v1(66.75,23.14) ; U1.P17 74.7,42.32 v1(75.03,41.99)
  BOTTOM w0.102: v1(75.03,41.99) 75.04,41.99 75.06,41.97 75.06,41.42 75.38,41.1 75.94,41.1 78.08,38.97 78.08,25.63 73.05,20.6 69.49,20.6 66.95,23.14 v1(66.75,23.14)
DDR3_A12: length 30.8
  TOP w0.102: v1(67.92,23.62) 67.91,23.63 68.17,23.89 68.17,25.15 UNK3U1.N7 ; v1(75.54,40.08) 75.54,40.57 75.08,41.02 74.69,41.02 U1.T17
  BOTTOM w0.102: v1(75.54,40.08) 77.24,38.38 77.24,26.01 72.67,21.44 69.82,21.44 67.92,23.34 v1(67.92,23.62)
DDR3_A13: length 29
  TOP w0.102: U1.R15 73.37,41.65 73.71,41.31 73.71,39.8 75.92,37.59 75.92,26.52 71.57,22.18 66.39,22.18 65.44,23.13 UNK3U1.T3
DDR3_A14: length 27.6
  TOP w0.1: UNK3U1.T7 68.55,23.14 v1(68.92,23.51)
  TOP w0.102: U1.R14 72.99,41.42 v1(73.01,41.42)
  BOTTOM w0.102: v1(73.01,41.42) 73.24,41.42 76.63,38.03 76.63,26.19 72.89,22.46 69.71,22.46 68.92,23.24 v1(68.92,23.51)
DDR3_A15: length 29.2
  TOP w0.102: v1(67.79,24.54) 67.79,25.57 UNK3U1.M7 ; v1(72.42,41.34) 72.09,41.02 U1.T13
  BOTTOM w0.102: v1(67.79,24.54) 67.97,24.72 69.16,24.72 69.64,24.23 69.64,23.88 69.82,23.7 70.4,23.7 70.53,23.57 71.62,23.57 72.08,24.03 73.43,24.03 75.92,26.52 75.92,37.63 74.14,39.41 74.14,40.13 73.22,41.05 72.71,41.05 v1(72.42,41.34)
DDR3_BA0: length 41
  TOP w0.102: U1.N16 74.06,42.97 74.25,42.78 74.81,42.78 75.97,41.62 75.97,39.66 77.24,38.39 77.24,26.01 72.11,20.88 65.78,20.88 64.71,21.95 63.95,21.95 62.53,23.37 62.53,25.49 62.97,25.94 64.16,25.94 UNK3U1.M2
DDR3_BA1: length 20.5
  TOP w0.102: UNK3U1.N8 69.76,25.94 73.27,25.94 74.44,27.1 74.44,37.19 72.64,38.99 72.28,38.99 71.62,39.65 71.62,39.83 71.44,40.01 U1.U12
DDR3_BA2: length 45
  TOP w0.102: U1.M16 74.17,43.62 74.51,43.28 74.98,43.28 76.5,41.76 76.5,40.13 77.8,38.84 77.8,25.76 72.36,20.32 65.27,20.32 62.23,23.37 62.23,25.91 63.05,26.74 64.94,26.74 UNK3U1.M3
DDR3_CAS: length 35.4
  TOP w0.102: v1(73.07,41.99) 73.39,42.32 U1.P15 ; UNK3U1.K3 66.32,27.93 67.41,26.85 v1(67.41,23.98)
  BOTTOM w0.102: v1(73.07,41.99) 76.93,38.13 76.93,26.11 73,22.18 69.56,22.18 68.42,23.31 68.42,23.62 68.06,23.98 v1(67.41,23.98)
DDR3_CKE0: length 19
  TOP w0.102: v1(73.05,28.17) 72.44,28.17 72.2,27.94 70.16,27.94 UNK3U1.K9 ; U1.P10 70.14,42.32 v1(69.82,41.99)
  BOTTOM w0.102: v1(73.05,28.17) 73,28.22 73,36.34 69.4,39.93 69.4,41.59 69.8,41.99 v1(69.82,41.99)
DDR3_CLKN: length 20.6
  TOP w0.102: v1(71.83,28.58) 72.92,29.67 72.92,36.25 71.07,38.1 UNK3C7.1 70.64,38.43 70.16,38.9 70.16,39.37 70.15,39.39 70.15,39.4 69.82,39.73 69.82,40.6 70.13,40.91 70.13,41.01 U1.T10 ; UNK3U1.K7 68.55,28.1 68.46,28.2 67.95,28.2 67.83,28.07 v1(67.8,28.04)
  BOTTOM w0.102: v1(71.83,28.58) 71.83,28.56 71.69,28.43 68.3,28.43 67.95,28.08 67.92,28.08 v1(67.8,28.04) 67.79,28.05 67.79,28.06 67.65,28.21 67.44,28.21 UNK3R2.2
DDR3_CLKP: length 19.4
  TOP w0.102: UNK3U1.J7 68.55,28.55 68.47,28.48 67.98,28.48 67.81,28.64 v1(67.76,28.68) ; U1.U9 69.54,40.32 69.54,39.6 69.88,39.26 69.88,38.79 70.35,38.32 UNK3C7.2 71.06,37.71 72.64,36.13 72.64,29.8 72.12,29.28 71.92,29.28 v1(71.9,29.26)
  BOTTOM w0.1: v1(67.76,28.68) 67.59,28.68 UNK3R2.1
  BOTTOM w0.102: v1(67.76,28.68) 67.82,28.64 67.88,28.7 71.34,28.7 v1(71.9,29.26)
DDR3_DQ0: length 7.1
  TOP w0.1: 63.62,36.06 63.62,36.06 UNK3U1.A2
  TOP w0.102: U1.T2 64.94,41.02 64.78,41.02 64.45,40.69 64.16,40.69 63.62,40.16 63.62,36.06
DDR3_DQ1: length 9.9
  TOP w0.102: U1.T3 65.58,41.01 65.58,40.87 65.27,40.57 65.27,39.79 64.94,39.46 64.94,36.79 66.01,35.73 66.01,33.66 65.48,33.13 65.17,33.13 64.77,33.53 UNK3U1.C2
DDR3_DQ2: length 8.3
  TOP w0.102: v1(68.42,35.98) 68.32,35.88 68.32,35.36 UNK3U1.A7 ; v1(67.21,41.99) U1.P6
  BOTTOM w0.102: v1(67.21,41.99) 67.21,41.99 67.64,41.57 67.64,41.02 67.31,40.69 67.31,37 68.3,36 68.4,36 v1(68.42,35.98)
DDR3_DQ3: length 10.3
  TOP w0.102: UNK3U1.D7 68.64,32.73 69.05,33.14 69.53,33.14 69.76,33.37 69.76,33.74 69.95,33.94 70.29,33.94 70.51,34.15 70.51,35.58 70.19,35.89 69.54,35.89 68.35,37.09 68.35,40.24 U1.U7
DDR3_DQ4: length 6.1
  TOP w0.102: U1.U1 63.93,40.01 63.93,36.29 64.63,35.59 64.89,35.59 UNK3U1.A3
DDR3_DQ5: length 7.6
  TOP w0.102: U1.U2 64.94,39.89 64.64,39.59 64.64,36.64 65.71,35.58 65.71,33.88 65.36,33.53 UNK3U1.C3
DDR3_DQ6: length 8.5
  TOP w0.102: UNK3U1.B8 v1(68.94,34.74) ; U1.R6 67.54,41.66 v1(67.28,41.4)
  BOTTOM w0.102: v1(67.28,41.4) 67.28,41.05 67,40.77 67,36.85 68.94,34.9 v1(68.94,34.74)
DDR3_DQ7: length 8.6
  TOP w0.102: U1.T7 68.19,40.87 67.86,40.55 67.86,40.22 68.04,40.05 68.04,36.96 69.74,35.26 69.74,34.21 69.35,33.81 UNK3U1.C8
DDR3_DQ8: length 15.3
  TOP w0.102: U1.T8 68.75,40.93 68.75,39.3 69.06,38.99 69.06,37.42 69.87,36.6 70.51,36.6 71.5,35.61 71.5,30.67 70.8,29.97 69.24,29.97 68.79,29.53 UNK3U1.H7
DDR3_DQ9: length 13.7
  TOP w0.102: U1.R2 64.93,41.69 64.75,41.69 64.4,41.34 63.98,41.34 62.91,40.27 62.91,36.58 62.12,35.79 62.12,32.49 62.78,31.83 63.34,31.83 63.65,31.52 64.16,31.52 UNK3U1.F2
DDR3_DQ10: length 16.2
  TOP w0.102: UNK3U1.H8 69.71,29.17 70.7,29.17 70.99,29.46 70.99,29.71 71.8,30.52 71.8,35.77 70.68,36.88 70.04,36.88 69.36,37.56 69.36,39 68.98,39.38 68.98,40.68 69.16,40.86 69.16,41.34 U1.R9
DDR3_DQ11: length 11
  TOP w0.1: UNK3U1.E3 65.35,31.96 v1(65.65,32.26)
  TOP w0.102: v1(65.91,41.34) U1.R4
  BOTTOM w0.102: v1(65.91,41.34) 65.73,41.16 65.73,36.68 66.54,35.87 66.54,34.4 65.39,33.25 65.39,32.52 v1(65.65,32.26)
DDR3_DQ12: length 14.9
  TOP w0.102: v1(68.49,41.96) U1.R7 ; v1(69.72,31.52) 69.72,31.5 UNK3U1.F8
  BOTTOM w0.102: v1(68.49,41.96) 68.25,41.59 68.25,41.2 68.35,41.1 68.35,38.64 70.07,36.91 70.65,36.91 71.8,35.76 71.8,32.29 71.04,31.52 v1(69.72,31.52)
DDR3_DQ13: length 17.4
  TOP w0.102: UNK3U1.H3 65.18,29.53 64.79,29.92 63.15,29.92 61.11,31.97 61.11,36.27 61.9,37.06 61.9,40.69 63.52,42.32 64.29,42.32 U1.P1
DDR3_DQ14: length 17
  TOP w0.102: UNK3U1.F7 68.56,31.13 v1(68.96,30.74) ; v1(69.21,42.04) 69.47,42.3 U1.P9
  BOTTOM w0.102: v1(69.21,42.04) 69.08,41.91 69.08,39.59 72.54,36.13 72.54,31.89 71.38,30.73 70.39,30.73 70,30.34 69.35,30.34 v1(68.96,30.74)
DDR3_DQ15: length 14.2
  TOP w0.102: UNK3U1.G2 64.14,30.74 63.41,30.74 61.82,32.32 61.82,35.92 62.61,36.71 62.61,40.39 63.9,41.68 64.28,41.68 U1.R1
DDR3_DQM0: length 10.4
  TOP w0.102: v1(66.56,41.34) U1.R5 ; UNK3U1.D3 65.63,32.73 v1(65.86,32.96)
  BOTTOM w0.102: v1(65.86,32.96) 65.86,33.17 66.87,34.19 66.87,36.05 66.06,36.86 66.06,40.84 v1(66.56,41.34)
DDR3_DQM1: length 15.8
  TOP w0.1: v1(68.07,31.93) UNK3U1.E7
  TOP w0.102: U1.P7 68.17,42.32 v1(67.93,42.08)
  BOTTOM w0.102: v1(67.93,42.08) 67.93,41.89 68.04,41.77 68.04,38.48 69.95,36.58 70.51,36.58 71.43,35.66 71.43,32.44 70.93,31.93 v1(68.07,31.93)
DDR3_DQSN0: length 7.9
  TOP w0.102: UNK3U1.B7 68.31,34.09 68.19,34.09 67.71,34.56 67.71,36.53 67.23,37.01 67.23,40.7 U1.T6
DDR3_DQSN1: length 13.3
  TOP w0.102: UNK3U1.G3 65.59,30.33 65.72,30.46 arc(65.75,30.53) 65.72,30.59 65.61,30.71 arc(65.58,30.77) 65.61,30.84 65.69,30.92 arc(65.75,30.95) 65.81,30.92 65.93,30.8 arc(66,30.77) 66.06,30.8 66.15,30.89 arc(66.18,30.95) 66.15,31.02 66.04,31.13 arc(66.01,31.19) 66.04,31.26 66.11,31.33 arc(66.18,31.36) 66.24,31.33 66.35,31.22 arc(66.42,31.19) 66.48,31.22 66.54,31.28 66.54,31.55 arc(66.52,31.61) 66.45,31.64 66.39,31.64 arc(66.33,31.66) 66.3,31.73 66.3,31.84 arc(66.33,31.9) 66.39,31.93 66.45,31.93 arc(66.52,31.96) 66.54,32.02 66.54,35.98 65.76,36.77 65.76,39.32 65.98,39.55 65.98,40.13 65.91,40.21 65.91,40.69 U1.T4
DDR3_DQSP0: length 7.6
  TOP w0.102: UNK3U1.C7 68.55,33.54 68.26,33.82 68.07,33.82 67.43,34.46 67.43,36.41 66.95,36.9 66.95,40.31 U1.U5
DDR3_DQSP1: length 13.3
  TOP w0.102: U1.U4 66.26,40.37 66.26,39.42 66.04,39.19 66.04,36.88 66.82,36.1 66.82,31.16 65.6,29.94 65.17,29.94 64.97,30.14 64.97,30.83 65.27,31.13 UNK3U1.F3
DDR3_NCS0: length 23.4
  TOP w0.102: UNK3U1.L2 64.97,27.55 66.2,27.55 v1(66.4,27.35) ; U1.U11 70.79,40.36 70.86,40.29 70.86,39.98 71.22,39.63 71.22,39.37 73.73,36.86 73.73,28.2 73.25,27.71 v1(72.54,27.71)
  BOTTOM w0.102: v1(72.54,27.71) 72.36,27.89 68.75,27.89 68.13,27.27 66.48,27.27 v1(66.4,27.35)
DDR3_ODT0: length 37.6
  TOP w0.1: v1(63.15,27.33) UNK3U1.K1
  TOP w0.102: v1(74.34,41.37) 74.34,41.37 U1.R16
  BOTTOM w0.102: v1(74.34,41.37) 75.19,40.52 75.63,40.52 77.52,38.64 77.52,25.89 72.79,21.16 69.69,21.16 65.5,25.35 65.5,26.04 64.74,26.8 63.69,26.8 v1(63.15,27.33)
DDR3_RAS: length 24.7
  TOP w0.102: v1(70.84,39.42) 70.84,39.63 70.58,39.88 70.58,40.06 70.48,40.16 70.48,40.57 70.74,40.82 70.74,40.92 70.81,41 U1.T11 ; v1(68.12,26.7) 68.12,26.86 66.25,28.73 UNK3U1.J3
  BOTTOM w0.102: v1(70.84,39.42) 71.17,39.42 73.73,36.86 73.73,27.84 72.59,26.7 v1(68.12,26.7)
DDR3_RST: length 37.9
  TOP w0.1: v1(64.71,22.57) 64.55,22.74 UNK3U1.T2
  TOP w0.102: v1(64.74,21.39) 65.53,20.6 72.23,20.6 77.52,25.89 77.52,38.64 76.22,39.93 76.22,41.68 74.87,43.03 74.43,43.03 74.17,43.29 73.72,43.29 U1.M15
  BOTTOM w0.1: v1(64.74,21.39) 64.69,21.44 UNK3C46.2 64.69,22.54 v1(64.71,22.57) 64.74,22.59 UNK3R8.1
DDR3_WE: length 28
  TOP w0.102: v1(66.7,25.28) 66.7,26.1 65.67,27.13 UNK3U1.L3 ; v1(72.64,25.55) 73.3,25.55 74.75,27 74.75,37.28 72.78,39.25 72.4,39.25 71.89,39.76 71.89,39.97 71.78,40.08 71.78,41.36 U1.R13
  BOTTOM w0.102: v1(66.7,25.28) 69.64,25.28 70.3,25.94 70.75,25.94 70.85,26.04 72.16,26.04 v1(72.64,25.55)
EMMC_1.8V: length 3.1
  BOTTOM w0.5: UNK4R5.2 C77.1 53.65,34.6 U55.5
GPIOX_16: length 7.5
  TOP w0.102: v1(69.82,49.15) 70.14,48.82 U1.D10
  BOTTOM w0.1: T125.1 68.98,55.14 68.98,52.57 70.05,51.5 70.05,50.43 69.88,50.27 69.88,49.21 v1(69.82,49.15)
GPIOX_17: length 5.1
  TOP w0.102: v1(68.51,49.15) U1.D8
  BOTTOM w0.1: T126.1 68.12,52.88 68.12,50.68 68.8,49.99 68.8,49.44 v1(68.51,49.15)
GPIOX_18: length 3.5
  TOP w0.102: v1(70.47,49.8) U1.C10
  BOTTOM w0.1: T127.1 70.45,52.03 70.79,51.69 70.79,50.12 v1(70.47,49.8)
GPIOZ_10: length 4.6
  TOP w0.1: U1.E2 64.85,48.26 64.11,48.26 62.48,49.89 62.48,50.5 62.38,50.6 UNK2T3.1
HW_VS: length 5
  TOP w0.102: v1(73.72,49.15) U1.D15
  BOTTOM w0.1: v1(73.72,49.15) 74.52,49.95 75.27,50.7 75.9,50.7 UNK2R15.2 76.3,52.22 UNK2R3.1
I2SIN_BCLK_C: length 170.3
  TOP w0.1: v2(91.65,25.05) 90.75,25.95 90.75,37.65 91.45,38.35 v2(91.45,44.2) v2(91.45,47) 91.45,56.25 90.8,56.9 90.8,59.85 v2(91.35,60.4) ; v2(86.75,20.7) 86.75,31.72 86.4,32.07 v2(86.4,44.2) ; v2(41.6,62.45) 40.15,62.45 38.35,60.65 v2(38.35,60.1) 38.35,58.75 38.7,58.4 38.7,52.55 38.5,52.35 38.5,50.6 39.15,49.95 39.15,38.9 v2(38.4,38.15) ; R107.2 v2(83.2,45.1)
  BOTTOM w0.1: 68.67,67.22 67.45,66 52.55,66 52,65.45 43.4,65.45 41.6,63.65 v2(41.6,62.45) ; UNK5R68.2 85,12.5 85.85,13.35 85.85,15.35 85.65,15.55 85.65,19.6 v2(86.75,20.7) ; v2(91.35,60.4) 91.35,61 91.15,61.2 86.5,61.2 84.95,62.75 82.3,62.75 80.9,64.15 80.9,68.5 79.4,70 73.3,70 71.9,68.6 70.05,68.6 69.88,68.42 ; v2(91.45,44.2) v2(86.4,44.2) 85.55,45.05 C103.2 84.1,45.1 v2(83.2,45.1) R343.2 ; R327.1 v2(38.35,60.1)
  BOTTOM w0.2: R229.1 v2(91.65,25.05) ; v2(38.4,38.15) R325.1 ; R227.1 v2(91.45,47)
  BOTTOM w0.3: 69.88,68.42 T309.1 68.67,67.22
I2SIN_DATA_C: length 40
  TOP w0.1: v2(87.3,50.3) 86.95,49.95 86.95,46.8 87.2,46.55 87.2,32.55 87.75,32 v2(87.75,21.62)
  BOTTOM w0.1: v2(87.3,50.3) R104.2 R103.2 ; v2(87.75,21.62) 86.62,21.62 85.1,20.1 85.1,15.1 UNK5R69.2
I2SIN_LRCK_C: length 173
  TOP w0.1: v2(87.75,47.5) 88,47.25 88,33.15 88.6,32.55 88.6,20.6 v2(88.45,20.45) ; v2(42.85,62.5) 41.05,60.7 41.05,59.7 39.75,58.4 39.75,52.15 39.95,51.95 39.95,49.4 v2(40.15,49.2) 39.95,49 v2(39.95,27.25) ; v2(84.75,47.5) 84.6,47.5 84.3,47.2 83.65,47.2 83.15,47.7 R344.2 82.45,47.6 82.1,47.25 78.85,47.25 78.5,46.9 C104.2 R108.2 ; v2(90.15,60.4) 90,60.25 v2(90,57.95) 90,56.1 90.4,55.7 90.4,48 v2(90.3,47.9) v2(90.3,38.55)
  BOTTOM w0.1: v2(88.45,20.45) 88.25,20.25 87.8,20.25 86.2,18.65 86.2,15.85 86.35,15.7 86.35,13.55 86.5,13.4 86.5,12.45 86.2,12.15 UNK5R67.2 ; v2(90.15,60.4) 89.95,60.6 85.9,60.6 84.6,61.9 81.9,61.9 80,63.8 80,68.15 79.05,69.1 75.55,69.1 74.88,68.42 ; v2(90.3,47.9) 89.9,47.5 v2(87.75,47.5) v2(84.75,47.5) ; 73.7,67.25 73.55,67.1 70.4,67.1 69.5,66.2 68.95,66.2 67.95,65.2 52.95,65.2 52.4,64.65 43.85,64.65 43.3,64.1 43.3,62.95 v2(42.85,62.5)
  BOTTOM w0.2: v2(90,57.95) 90.1,57.85 R228.1 ; v2(40.15,49.2) 40.15,49.25 39.95,49.45 R328.1 ; R230.1 89.8,35.5 89.8,38.05 v2(90.3,38.55) ; R326.1 v2(39.95,27.25)
  BOTTOM w0.3: 73.7,67.25 T307.1 74.88,68.42
I2SIN_MCLK_B: length 39.5
  TOP w0.1: v2(85.3,22.35) 85.75,22.8 85.75,31.55 85.6,31.7 85.6,45.35 v2(86.4,46.15) ; R102.2 v2(83.1,46.2)
  BOTTOM w0.1: UNK5R70.2 83.65,15.6 84.5,16.45 84.5,20.6 85.3,21.4 v2(85.3,22.35) ; v2(83.1,46.2) 83.45,46.55 86,46.55 v2(86.4,46.15)
I2SO_DATA0: length 125.4
  TOP w0.1: v2(39.55,29.8) 39.75,30 39.75,51.85 39.55,52.05 39.55,58.5 40.85,59.8 40.85,61.05 v2(41.05,61.25) ; v2(89.45,49.4) 89.25,49.6 89.25,55.19 v2(89.4,55.34) 89.25,55.49 89.25,61.6 v2(89.85,62.2)
  BOTTOM w0.1: v2(89.85,62.2) 89.85,62.8 88.95,63.7 R225.2 88.4,63.75 87.9,64.25 82.45,64.25 82.05,64.65 82.05,69.05 80,71.1 72.8,71.1 71.4,69.7 67.65,69.7 64.75,66.8 52.15,66.8 51.6,66.25 43,66.25 40.5,63.75 40.5,61.8 v2(41.05,61.25) ; v2(89.45,49.4) 89.6,49.25 89.6,48.6 89.15,48.15 83.9,48.15 R231.2 83.35,47.7 C105.2 81.45,47.7 R109.2
  BOTTOM w0.2: v2(39.55,29.8) 38.9,29.8 38.55,30.15 36.85,30.15 36.66,30.34 U301.7 ; U201.7 93.39,54.8 93.2,54.99 91.5,54.99 91.15,55.34 v2(89.4,55.34)
I2SO_DATA1: length 120.1
  TOP w0.1: v2(40.45,60.45) 40.45,59.7 39.3,58.55 v2(39.3,51.75) ; v2(89.9,33.4) 89.2,34.1 89.2,48.7 v2(89.15,48.75) 89,48.9 89,61.95 v2(89.25,62.2)
  BOTTOM w0.1: R110.2 C106.2 83.15,48.75 83.5,49.1 R231.1 83.9,49.1 84.65,48.35 88.75,48.35 v2(89.15,48.75) ; v2(40.45,60.45) 40.3,60.6 40.3,63.85 42.9,66.45 51.5,66.45 52.05,67 64.67,67 67.57,69.9 71.32,69.9 72.72,71.3 80.15,71.3 82.25,69.2 82.25,64.75 82.55,64.45 88.5,64.45 90.25,62.7 90.25,62 90.05,61.8 89.65,61.8 v2(89.25,62.2) 88.8,62.2 R226.2
  BOTTOM w0.2: U202.7 93.39,32.86 93.2,33.05 91.5,33.05 91.15,33.4 v2(89.9,33.4) ; v2(39.3,51.75) 38.9,51.75 38.55,52.1 36.85,52.1 36.66,52.29 U302.7
I2SO_MCLK_A: length 1.1
  TOP w0.1: T101.1 R101.2
IR_IN: length 4.6
  TOP w0.1: UNK2T6.1 73.16,52.23
  TOP w0.102: 73.16,52.23 73.16,51.17 73.07,51.08 73.07,50.44 U1.B14
IR_OUT: length 10.5
  TOP w0.102: U1.B13 72.1,50.34 72.44,50.68 72.44,53.11 76.71,57.39 UNK2T5.1
LCD_BL_EN: length 26.4
  TOP w0.1: v2(60.9,63.7) 61.19,63.41 61.19,57.61 61.5,57.3 61.5,54.12 62.28,53.34 62.28,52.53 63.72,51.09 63.72,50.52 64.11,50.12 U1.B1
  BOTTOM w0.1: v2(60.9,63.7) 60.5,64.1 60,64.1 59.6,63.7 59.1,63.7 58.3,62.9 51.2,62.9 50.99,63.11
  BOTTOM w0.3: UNK2T21.1 50.99,63.11
LCD_BL_PWM: length 30
  TOP w0.102: v2(59.4,63.1) 59.4,62.6 60.1,61.9 60.1,58.9 59.7,58.5 59.7,57 60,56.7 v2(60,55.5)
  TOP w0.127: v1(68.45,49.74) 68.44,49.74 68.19,49.48 U1.C7
  BOTTOM w0.1: v1(68.45,49.74) 68.45,49.89 67.92,50.42 67.92,52.18 64.95,55.15 63.25,55.15 62.92,55.48 60.02,55.48 v2(60,55.5) ; 51.1,62.2 51.4,62.5 58.5,62.5 59.1,63.1 v2(59.4,63.1)
  BOTTOM w0.3: 51.1,62.2 UNK2T22.1
LCD_RESET: length 26.1
  TOP w0.1: U1.C2 64.8,49.47 64.47,49.8 64.12,49.8 63.51,50.41 63.51,50.99 62.07,52.43 62.07,53.24 61.3,54.01 61.3,57.2 60.96,57.54 60.96,62.94 v2(60.2,63.7)
  BOTTOM w0.1: 53.1,62.2 53.2,62.3 58.6,62.3 59,62.7 60.35,62.7 60.6,62.95 60.6,63.3 v2(60.2,63.7)
  BOTTOM w0.3: 53.1,62.2 UNK2T24.1
LINE_OUT_DET: length 25.4
  TOP w0.1: v2(59.4,64.1) 59.8,63.7 59.8,62.8 60.55,62.05 60.55,57.35 60.9,57 60.9,53.8 61.67,53.04 61.67,52.22 63.09,50.8 63.09,50.22 64.16,49.15 64.61,49.15 U1.D2
  BOTTOM w0.1: v2(59.4,64.1) 58.9,64.6 53.5,64.6 53.3,64.4
  BOTTOM w0.3: UNK2T23.1 53.3,64.4
LINUX_RX: length 23.7
  TOP w0.1: UNK2D4.1 66.91,65.21 UNK2R1.2
  TOP w0.102: UNK2D4.1 68.44,65.21 69.55,64.1 72.45,64.1 75.69,60.86 75.69,57 72,53.32 72,51.19 71.77,50.95 71.77,50.45 U1.B12
LINUX_TX: length 32.2
  TOP w0.1: v2(64.55,64.35) 64.25,64.35 63.85,64.75 UNK2D3.1 64.89,65.21 UNK2R16.2 ; v2(70.6,66.1) 69.7,66.1 69.2,65.6 69.2,64.8 69.65,64.35 71.4,64.35
  TOP w0.102: U1.A13 72.22,50.9 72.22,53.23 75.9,56.91 75.9,60.95 72.5,64.35 71.4,64.35
  BOTTOM w0.1: v2(70.6,66.1) 70.3,66.1 69.8,65.6 69.3,65.6 68.3,64.6 64.8,64.6 v2(64.55,64.35)
LRCK: length 4.9
  BOTTOM w0.102: J813.10 89.18,8.77 88.05,9.9 87.25,9.9 86.2,10.95 UNK5R67.1
MCLK: length 5.8
  BOTTOM w0.1: UNK5R70.1 83.65,10.1 85.05,8.7 86.95,8.7 87.18,8.47 J813.14
MDDR3_VREF1: length 12.2
  TOP w0.3: v1(62.99,29.24) 63.28,29.53 UNK3U1.H1 ; UNK3U1.M8 68.96,25.94 v1(68.95,25.94)
  BOTTOM w0.254: 63.09,28.91 62.99,29.01 62.99,29.19 ; 63.09,28.91 64.36,27.64 65.17,27.64 66.42,26.39 67.46,26.39 67.96,25.9 UNK3C40.2 ; 63.09,28.91 63.09,29.09 62.99,29.19 ; v1(62.99,29.24) 62.99,29.19
  BOTTOM w0.3: UNK3R19.1 UNK3R20.2 UNK3C27.2 62.93,29.24 v1(62.99,29.24)
  BOTTOM w0.4: v1(68.95,25.94) 68.91,25.9 UNK3C40.2
NAND_ALE: length 39.2
  TOP w0.1: v2(47.2,29.8) 47.4,29.6 51.8,29.6 52.64,30.44 UNK4U5.17 52.64,32.34 53.3,33 54.75,33 57.4,35.65 57.4,39.1 ; UNK4U9.U5 v2(48.5,40.1)
  TOP w0.102: 57.4,39.1 57.4,41.5 58.05,42.15 61.65,42.15 63.02,43.52 64.19,43.52 U1.M1
  BOTTOM w0.1: v2(47.2,29.8) 47.2,34.55 46.8,34.95 46.8,38.4 v2(48.5,40.1)
NAND_CLE: length 39.5
  TOP w0.1: v2(49,39.55) 49.01,39.54 UNK4U9.W5 ; v2(47.7,30.15) 48.05,29.8 51.7,29.8 52.14,30.24 UNK4U5.16 52.14,32.19 53.15,33.2 54.65,33.2 57.15,35.7 57.15,41.55 58,42.4 61.6,42.4 63.04,43.84 63.35,43.84
  TOP w0.102: U1.L2 64.61,43.94 64.08,43.94 63.98,43.84 63.35,43.84 63.35,43.84
  BOTTOM w0.1: v2(49,39.55) 48.25,39.55 47.5,38.8 47.5,38.05 47,37.55 47,35.65 UNK4R14.2 47.4,34.95 47.4,30.45 v2(47.7,30.15)
NAND_CS1: length 36.8
  TOP w0.1: UNK4U9.W6 50.51,38.1 50.51,36.35 v2(50.16,36) ; UNK4R11.2 UNK4R11.1 UNK4C3.2 58.89,43.3 57.55,43.3 56.3,42.05 56.3,36.15 54.1,33.95 53,33.95 52.45,33.4 49,33.4 48.64,33.04 UNK4U5.9 48.64,30.36 v2(48.65,30.35)
  TOP w0.102: UNK4R11.2 62.53,43.79 62.9,44.16 64.19,44.16 64.19,44.17 U1.L1
  BOTTOM w0.1: v2(48.65,30.35) UNK4R1.1 49.26,35.1 v2(50.16,36)
NAND_D0: length 28.6
  TOP w0.1: v2(54.15,52.75) 54.14,52.74 UNK4U5.29 54.14,50.3 54.35,50.09 55.51,50.09 56,49.6 60.02,49.6 60.57,49.05 UNK4R19.1 UNK4R19.2 62.2,49.05 63.39,47.86 64.45,47.86 64.79,47.52 U1.F2 ; UNK4U9.H3 48.01,44.99 v2(48,45)
  BOTTOM w0.1: v2(48,45) 48.65,44.35 50.1,44.35 UNK4R16.2 50.9,46.3 51.1,46.5 51.1,50.8 51.51,51.21 53.76,51.21 54.15,51.6 v2(54.15,52.75)
NAND_D1: length 26.9
  TOP w0.1: U1.F1 64.21,47.6 63.14,47.6 62.28,48.47 60.45,48.47 59.86,49.05 UNK4R20.2 UNK4R20.1 56.1,49.05 55.37,49.79 54.05,49.79 53.64,50.19 UNK4U5.30 53.64,52.34 v2(53.65,52.35) ; v2(48.5,45.45) 48.51,45.44 UNK4U9.H4
  BOTTOM w0.1: v2(53.65,52.35) 52.81,51.51 51.41,51.51 50.8,50.9 50.8,46.8 50.3,46.3 50.3,45.2 49.7,44.6 48.75,44.6 48.5,44.85 v2(48.5,45.45)
NAND_D2: length 26.2
  TOP w0.1: v2(49,45) 49.01,44.99 UNK4U9.H5 ; v2(53.15,52.75) 53.14,52.74 UNK4U5.31 53.14,50.19 53.84,49.48 55.22,49.48 56.34,48.36 59.84,48.36 60.37,47.83 UNK4R21.1 UNK4R21.2 62.4,47.83 63.36,46.87 U1.G1
  BOTTOM w0.1: v2(49,45) 49.65,45 49.95,45.3 49.95,46.66 50.49,47.2 50.49,51 51.31,51.82 52.73,51.82 53.15,52.24 v2(53.15,52.75)
NAND_D3: length 29.6
  TOP w0.1: UNK4U9.J2 46.7,44.1 46.45,44.35 46.45,46 46.7,46.25 47.65,46.25 v2(48,46.6) ; U1.G2 64.72,46.87 64.38,46.54 62.99,46.54 62.28,47.25 60.45,47.25 59.86,47.83 UNK4R22.2 UNK4R22.1 56.42,47.83 55.07,49.18 53.74,49.18 52.64,50.28 UNK4U5.32 52.64,52.34 v2(52.65,52.35)
  BOTTOM w0.1: v2(52.65,52.35) 52.42,52.12 51.2,52.12 50.19,51.11 50.19,47.84 48.95,46.6 v2(48,46.6)
NAND_D4: length 31.3
  TOP w0.1: v2(47.05,45.8) 47.51,45.34 47.51,44.6 UNK4U9.J3 ; UNK4R52.2 47.78,53.32 48.14,52.96 v2(48.14,52.35) UNK4U5.41 48.14,50.21 48.59,49.75 52.76,49.75 53.64,48.87 54.93,48.87 56.55,47.25 59.94,47.25 60.58,46.61 UNK4R23.1 UNK4R23.2 62.12,46.33 63.5,46.33 63.93,45.9 64.62,45.9 U1.H2
  BOTTOM w0.1: v2(47.05,45.8) 47.05,46.25 47.6,46.8 47.6,51.81 v2(48.14,52.35)
NAND_D5: length 36.3
  TOP w0.1: UNK4U9.J4 47.51,43.1 46.05,43.1 45.7,43.45 v2(45.7,45.8) ; UNK4R10.2 46.9,53.58 47.64,52.84 v2(47.64,52.8) UNK4U5.42 47.64,49.89 48.1,49.43 52.67,49.43 53.58,48.53 54.77,48.53 56.45,46.85 58.26,46.85 UNK4R24.1 UNK4R24.2 59.94,46.61 60.52,46.03 63.19,46.03 63.65,45.57 U1.J1
  BOTTOM w0.1: v2(45.7,45.8) 45.7,45.95 46.7,46.95 46.7,51.86 v2(47.64,52.8)
NAND_D6: length 34.6
  TOP w0.1: U1.J2 64.64,45.27 62.94,45.27 62.81,45.39 61.84,45.39 UNK4R25.2 UNK4R25.1 60.27,45.39 59.63,46.03 58.27,46.03 57.8,46.5 56.3,46.5 54.6,48.2 53.45,48.2 52.52,49.13 48,49.13 47.14,49.99 v2(47.14,50) UNK4U5.43 47.14,52.91 46.9,53.15 45.77,53.15 UNK4R13.2 ; v2(49,43.1) 49.01,43.11 UNK4U9.J5
  BOTTOM w0.1: v2(49,43.1) 48.15,43.1 46.5,44.75 46.5,46.3 47.14,46.94 v2(47.14,50)
NAND_D7: length 39.8
  TOP w0.1: v2(45.7,46.6) 46.2,47.1 48.75,47.1 50.51,45.34 50.51,44.6 50.01,44.1 UNK4U9.J6 ; U1.K1 62.59,44.92 62.58,44.91 59.88,44.91 UNK4R26.2 UNK4R26.1 58.5,45.5 57.85,46.15 56.1,46.15 54.35,47.9 53.25,47.9 52.33,48.82 47.63,48.82 46.64,49.81 UNK4U5.44 v2(46.64,52.73) 46.47,52.9 44.8,52.9 UNK4R2.2
  BOTTOM w0.1: v2(46.64,52.73) 46.64,52.19 46.39,51.94 46.39,47.29 v2(45.7,46.6)
NAND_NR/B: length 43
  TOP w0.1: v2(45.65,34.4) 47.14,32.91 UNK4U5.6 47.14,30.68 47.26,30.57 47.52,30.57 47.64,30.69 UNK4U5.7 47.64,32.56 47.6,32.6 47.6,33.25 48.6,34.25 52.1,34.25 52.65,34.8 53.7,34.8 55.1,36.2 55.1,38.9 55.7,39.5 55.7,42.45 v2(57.6,44.35)
  TOP w0.102: U1.K3 65.59,44.92 v1(65.91,44.59)
  BOTTOM w0.1: 58.59,43.36 v2(57.6,44.35) ; v2(45.65,34.4) 45.3,34.75 UNK4R12.1 UNK4R9.1 UNK4R17.1
  BOTTOM w0.102: 58.59,43.36 62.2,43.36 62.83,43.99 63.14,43.99 63.83,44.68 64.43,44.68 64.63,44.88 65.62,44.88 v1(65.91,44.59)
NAND_NRE: length 25.9
  TOP w0.1: v2(55.5,38.75) 55.3,38.55 55.3,36.1 53.8,34.6 52.75,34.6 52.2,34.05 48.7,34.05 47.8,33.15 47.8,32.8 48.14,32.46 UNK4U5.8 ; UNK4R18.2 UNK4R18.1 58.95,40.85 v2(58.95,38.75)
  TOP w0.102: U1.M2 64.61,43.29 63.09,43.29 61.39,41.6 UNK4R18.2
  BOTTOM w0.1: v2(58.95,38.75) v2(55.5,38.75)
NAND_NWE: length 18.1
  TOP w0.1: UNK4U5.18 53.14,32.44 53.5,32.8 54.9,32.8 59.35,37.25 59.35,40.15 UNK4R15.1 UNK4R15.2
  TOP w0.102: U1.N1 63.07,42.97 UNK4R15.2
NAND_PSL: length 2.5
  TOP w0.102: UNK4R3.2 49.14,53.43 UNK4U5.39
NAND_VSP: length 3.5
  TOP w0.1: v2(50.08,53.04) 50.21,53.16 UNK4R8.2
  TOP w0.102: UNK4U5.38 49.64,52.59 v2(50.08,53.04)
  BOTTOM w0.1: v2(50.08,53.04) 50.55,53.5 UNK4R7.2
NPWM_OFF1: length 54.2
  TOP w0.1: v2(93.15,19.9) 93.5,20.25 93.5,23.05 94.1,23.65 94.1,35.65 v2(94.25,35.8) 94.1,35.95 v2(94.1,57.7) ; v2(92.9,14) 91.8,14 90.1,12.3 88.55,12.3 R219.2
  BOTTOM w0.1: v2(93.15,19.9) 93.3,19.75 93.3,14.4 v2(92.9,14)
  BOTTOM w0.2: U201.12 95.18,57.37 94.85,57.7 v2(94.1,57.7) ; v2(94.25,35.8) 95,35.8 95.18,35.62 U202.12
NPWM_OFF2: length 39.6
  TOP w0.1: v2(35.7,49.4) 35.9,49.2 35.9,47.5 35.45,47.05 35.45,36.85 35.9,36.4 35.9,27.7 v2(35.7,27.5) 35.58,27.38 35.58,22.73 v2(35.77,22.52)
  BOTTOM w0.1: R320.2 42.8,26 41.6,24.8 39.25,24.8 36.6,22.15 36.15,22.15 v2(35.77,22.52)
  BOTTOM w0.2: v2(35.7,27.5) 35.2,27.5 34.87,27.83 U301.12 ; v2(35.7,49.4) 35.1,49.4 34.87,49.63 U302.12
NRESET_AMP: length 119.9
  TOP w0.1: R216.1 88.53,14.6 86.23,16.9 78.6,16.9 78.4,16.7 77.74,16.7 v2(77.34,16.3) ; v2(58.7,25) 59.1,24.6 59.7,24.6 60.55,23.75 60.55,23.33 66.4,17.48 v2(66.4,17.3) ; U1.B6 67.21,50.45 67.21,50.99 67.41,51.18 67.41,52.91 66.54,53.77 66.54,59.11 v2(66.2,59.45) ; v2(42.15,56.85) 42.55,56.45 42.55,27.45 43.85,26.15 46.3,26.15 47.15,25.3 v2(47.15,24.8)
  BOTTOM w0.1: R316.1 v2(47.15,24.8) 47.2,24.8 48.2,25.8 57.9,25.8 v2(58.7,25) ; v2(77.34,16.3) 76.94,16.3 76.74,16.5 67.75,16.5 67.35,16.9 66.8,16.9 v2(66.4,17.3) ; v2(66.2,59.45) 66,59.25 57.4,59.25 57.1,59.55 54.5,59.55 54.1,59.15 54.1,58.25 52.9,57.05 42.35,57.05 v2(42.15,56.85)
NRST_AMP1: length 52.6
  TOP w0.1: v2(92.9,14.6) R240.2 91.9,14.6 91.3,14 90.55,14 R215.2 R216.2 ; v2(92.5,19.9) 93.3,20.7 93.3,23.45 v2(93.45,23.6) 93.85,24 93.85,45.3 v2(93.7,45.45)
  BOTTOM w0.1: v2(92.9,14.6) 93.05,14.75 93.05,19.35 v2(92.5,19.9)
  BOTTOM w0.2: v2(93.7,45.45) 94.6,45.45 94.9,45.75 94.9,46.55 95.35,47 C204.2 96.68,47.56 U201.36 ; v2(93.45,23.6) 93.45,23.55 93.5,23.5 94.7,23.5 94.85,23.65 94.85,24.55 95.35,25.05 C226.2 96.68,25.61 U202.36
NRST_AMP2: length 69.2
  TOP w0.1: v2(36.38,22.52) 35.77,23.12 35.77,27.02 36.1,27.35 36.1,36.5 35.65,36.95 35.65,39.65 v2(35.85,39.85) 35.65,40.05 35.65,46.95 36.1,47.4 v2(36.1,61.75)
  BOTTOM w0.1: v2(36.38,22.52) 36.69,22.52 39.16,25 41.4,25 42.85,26.45 45,26.45 R338.2 R315.2 R316.2
  BOTTOM w0.2: v2(36.1,61.75) 35.2,61.75 34.85,61.4 34.85,60.25 34.69,60.09 C326.2 33.92,60.09 33.5,59.67 33.5,58.85 33.37,58.72 U302.36 ; v2(35.85,39.85) 35.3,39.85 34.85,39.4 34.85,38.3 34.69,38.14 C304.2 33.5,37.71 33.5,36.9 33.37,36.77 U301.36
